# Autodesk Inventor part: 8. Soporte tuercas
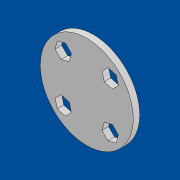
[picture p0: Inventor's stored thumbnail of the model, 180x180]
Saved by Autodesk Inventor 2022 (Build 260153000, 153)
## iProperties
Created: 2022-05
Part Number: 8. Soporte tuercas
Material: Genérico
Document SubType Name: Modeling
Designer: pined
Density: 1 g/cm^3
Appearance: Valor por defecto
Author: pined
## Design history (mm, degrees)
sketch "Boceto1" dims "d2" = 25
  geometry: L1 (0, 0)-(0, 25); L2 (0, 0)-(-19.506, 19.506); C1 r 17.5 at (0, 0); C2 r 7.5 at (0, 0); C3 r 1.5 at (-8.839, 8.839); C4 r 1.5 at (-8.839, -8.839); C5 r 1.5 at (8.839, -8.839); C6 r 1.5 at (8.839, 8.839); 1 further point
  constraints: 6 centre point, 4 end point, 3 coincident, 1 point on line, 1 vertical, 12 other
  dimensions: "d0" = 35 diameter of C1; "d1" = 15 diameter of C2; "d3" = 45 deg angle of L1 L2; "d4" = 3 diameter of C3; "d7" = 360 deg dimension on point (0, 0) C3.centre (derived)
extrude "Extrusión1" new body sketch "Boceto1" distance "d9" = 2.5; taper "d10" = 0 deg
sketch "Boceto2"
  geometry: L1 (-6.593, 6.593)-(-9.661, 5.772); L2 (-9.661, 5.772)-(-11.906, 8.017); L3 (-11.906, 8.017)-(-11.084, 11.084); L4 (-11.084, 11.084)-(-8.017, 11.906); L5 (-8.017, 11.906)-(-5.772, 9.661); L6 (-5.772, 9.661)-(-6.593, 6.593); L7 (-9.661, -5.772)-(-6.593, -6.593); L8 (-6.593, -6.593)-(-5.772, -9.661); L9 (-5.772, -9.661)-(-8.017, -11.906); L10 (-8.017, -11.906)-(-11.084, -11.084); L11 (-11.084, -11.084)-(-11.906, -8.017); L12 (-11.906, -8.017)-(-9.661, -5.772); L13 (5.772, -9.661)-(6.593, -6.593); L14 (6.593, -6.593)-(9.661, -5.772); L15 (9.661, -5.772)-(11.906, -8.017); L16 (11.906, -8.017)-(11.084, -11.084); L17 (11.084, -11.084)-(8.017, -11.906); L18 (8.017, -11.906)-(5.772, -9.661); L19 (9.661, 5.772)-(6.593, 6.593); L20 (6.593, 6.593)-(5.772, 9.661); L21 (5.772, 9.661)-(8.017, 11.906); L22 (8.017, 11.906)-(11.084, 11.084); L23 (11.084, 11.084)-(11.906, 8.017); L24 (11.906, 8.017)-(9.661, 5.772); C1 r 17.5 at (0, 0) reference; C2 r 1.5 at (8.839, 8.839) reference; C3 r 1.5 at (8.839, -8.839) reference; C4 r 1.5 at (-8.839, -8.839) reference; C5 r 1.5 at (-8.839, 8.839) reference; 2 further points
  constraints: 48 end point, 1 coincident, 62 other
  dimensions: "d11" = 5.5 distance between parallel lines of L5 L2; "d14" = 360 deg dimension on point (0, 0) L5.end (derived)
extrude "Extrusión2" join sketch "Boceto2" distance "d16" = 2.5; taper "d17" = 0 deg
sketch "Boceto3"
  geometry: C1 r 17.5 at (0, 0) reference; C2 r 1.5 at (-8.839, 8.839) reference; C3 r 1.5 at (-8.839, -8.839) reference; C4 r 1.5 at (8.839, -8.839) reference; C5 r 1.5 at (8.839, 8.839) reference; 1 further point
extrude "Extrusión3" cut sketch "Boceto3" distance "d18" = 2.54; taper "d19" = 0 deg
node "Sólido1"
node "Contorno proyectado1"
node "Contorno proyectado2"
